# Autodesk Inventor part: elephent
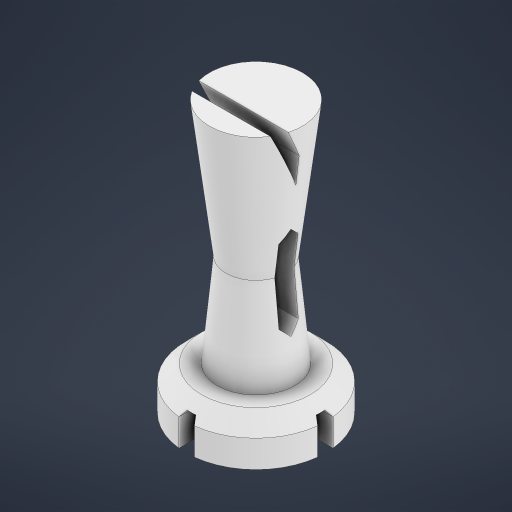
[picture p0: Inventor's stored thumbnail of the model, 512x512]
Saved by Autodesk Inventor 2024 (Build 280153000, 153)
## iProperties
Created: 2025-07
Part Number: elephent
Material: ABS Plastic
Document SubType Name: Modeling
Designer: acer
Density: 1.06 g/cm^3
Appearance: Smooth - White
Author: acer
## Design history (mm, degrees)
sketch "Sketch1"
  geometry: L1 (0, 0)-(0, 9); L2 (0, 0)-(35, 0); L3 (0, 9)-(5.5, 9); L4 (5.5, 9)-(5.5, 5); L5 (5.5, 5)-(17.5, 3.869); L6 (17.5, 3.869)-(35, 5.993); L7 (35, 5.993)-(35, 0)
  constraints: 14 end point, 2 horizontal, 1 parallel, 1 perpendicular, 1 vertical
  dimensions: "d0" = 9 distance of L1.start L1.end; "d2" = 35 distance of L1.start L2.end; "d3" = 5.5 distance of L1.end L3.end; "d4" = 4 distance of L3.end L4.end
revolve "Revolution1" sketch "Sketch1" stored, may be unused: angle "d5" = 90 deg
chamfer "Chamfer1" distance "d6" = 2; stored, may be unused: second distance "d7" = 2, angle "d8" = 45 deg
sketch "Sketch2"
  geometry: L1 (35, -5.993)-(35, 5.993) reference; L2 (35, 0)-(28, 0); L3 (28, 0)-(35, 3.205); L4 (35, 3.205)-(35, 1.602); L5 (35, 1.602)-(29.091, -1.103); 2 further points
  constraints: 8 end point, 2 point on line, 1 horizontal, 1 midpoint, 1 parallel
  dimensions: "d9" = 7 distance of L2.start L2.end
extrude "Extrusion1" cut sketch "Sketch2" stored distance "d10" = 20; taper "d11" = 0 deg
sketch "Sketch3"
  geometry: L1 (17.5, -3.869)-(17.5, 3.869) reference; L2 (17.5, 0)-(21.5, 0); L3 (17.5, 0)-(12, 0); L4 (12, -1.25)-(10.75, 0); L5 (10.75, 0)-(12, 1.25); L6 (12, 1.25)-(21.5, 1.25); L7 (21.5, 1.25)-(22.75, 0); L8 (22.75, 0)-(21.5, -1.25); L9 (21.5, -1.25)-(12, -1.25); A1 r 1.25 centre (21.5, 0) between (21.5, 1.25) and (22.75, 0); A2 r 1.25 centre (12, 0) between (12, -1.25) and (10.75, 0); 1 further point
  constraints: 16 end point, 6 point on circle, 4 perpendicular, 2 centre point, 2 coincident, 2 tangent, 1 horizontal, 1 midpoint
  dimensions: "d12" = 4 distance of L2.start L2.end; "d13" = 5.5 distance of L2.start L3.end; "d14" = 2.5 diameter of A1; "d15" = 2.5 diameter of A2
extrude "Extrusion2" cut sketch "Sketch3" stored distance "d16" = 20; taper "d17" = 0 deg
sketch "Sketch4"
  geometry: L1 (5.5, -5)-(5.5, 5) reference; L2 (-5.5, 1)-(5.5, 1); L3 (5.5, 1)-(5.5, -1); L4 (5.5, -1)-(-5.5, -1); L5 (-5.5, -1)-(-5.5, 1); L6 (-5.5, 1)-(5.5, -1); L7 (5.5, 1)-(-5.5, -1); L8 (5.5, 0)-(5, 0); L9 (5, 0)-(3.5, 1); L10 (3.5, -9)-(3.5, 9) reference; L11 (5, 0)-(3.5, -1); 1 further point
  constraints: 18 end point, 5 point on line, 3 midpoint, 2 horizontal, 2 parallel, 1 perpendicular
  dimensions: "d18" = 2 distance of L2.end L3.end; "d19" = 0.5 distance of L8.start L8.end
extrude "Extrusion3" cut sketch "Sketch4" stored distance "d20" = 20; taper "d21" = 0 deg
chamfer "Chamfer2" distance "d22" = 1; stored, may be unused: second distance "d23" = 2, angle "d24" = 45 deg
sketch "Sketch5"
  geometry: L1 (5, 5.5)-(-5, 5.5) reference; L2 (-1, -5.5)-(1, -5.5); L3 (1, -5.5)-(1, 5.5); L4 (1, 5.5)-(-1, 5.5); L5 (-1, 5.5)-(-1, -5.5); L6 (-1, -5.5)-(1, 5.5); L7 (1, -5.5)-(-1, 5.5); L8 (0, 5.5)-(0, 5); L9 (0, 5)-(1, 3.5); L10 (-8.944, 3.5)-(8.944, 3.5) reference; L11 (0, 5)-(-1, 3.5); 1 further point
  constraints: 18 end point, 5 point on line, 3 midpoint, 2 parallel, 1 horizontal, 1 perpendicular, 1 vertical
  dimensions: "d25" = 2 distance of L4.end L3.end; "d26" = 0.5 distance of L8.start L8.end
extrude "Extrusion4" cut sketch "Sketch5" stored distance "d27" = 20; taper "d28" = 0 deg
chamfer "Chamfer3" distance "d29" = 1; stored, may be unused: second distance "d30" = 2, angle "d31" = 45 deg
body "Solid1"
